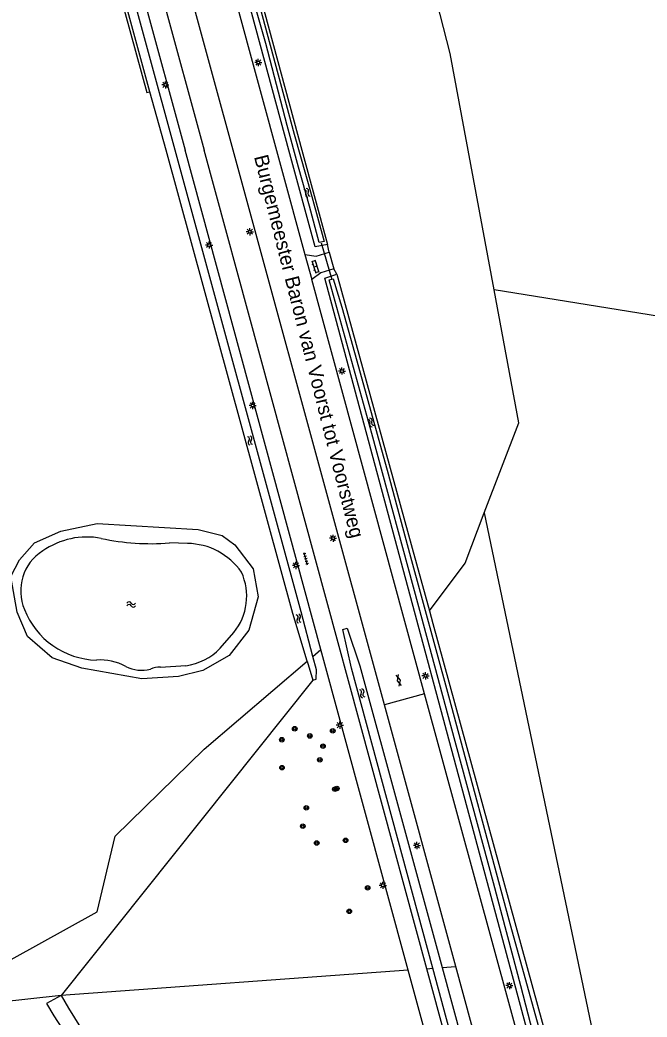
# Model space of a CAD drawing. Extents: x 128999 to 131010, y 395498 to 399007.
# Drawn here: x 129345.3 to 129455.1, y 397348.1 to 397522.8 of the extents above; entities that cross this region are included whole.
import ezdxf

# ---------------------------------------------------------------- set-up
doc = ezdxf.new("R2010")
doc.units = 0
for name, color, linetype in [('gg-afsc-faunaraster', 7, 'Continuous'), ('gg-anno-openbare ruimte label', 7, 'Continuous'), ('gg-knt-onverhard', 7, 'Continuous'), ('gg-knt-verharding', 7, 'Continuous'), ('gg-kntw-bovenkant insteek waterloop', 7, 'Continuous'), ('gg-kntw-waterlijn', 7, 'Continuous'), ('gg-kwrk-duiker nz buis', 7, 'Continuous'), ('gt-grn-groengrens', 7, 'Continuous'), ('gt-grn-vlakafsluiter', 7, 'Continuous'), ('gt-grn-weggrens', 7, 'Continuous'), ('gt-symb-boom', 7, 'Continuous'), ('gt-symb-gesloten verharding', 7, 'Continuous'), ('gt-symb-klinker verharding', 7, 'Continuous'), ('gt-symb-lichtmast', 7, 'Continuous'), ('gt-symb-tegel verharding', 7, 'Continuous'), ('gt-symb-watersymbool', 7, 'Continuous')]:
    doc.layers.add(name, color=color, linetype=linetype)

# ---------------------------------------------------------------- blocks, each defined once
blk = doc.blocks.new('gt0-BOOM')
at = {"layer": 'gt-symb-boom'}
for radius in [0.4, 0.2]:
    blk.add_circle((0, 0), radius, dxfattribs=at)
blk = doc.blocks.new('gt0-LMAST')
at = {"layer": 'gt-symb-lichtmast'}
for p, q in [((-0.18, 0.17), (-0.45, 0.44)), ((-0.01, 0.25), (-0.01, 0.62)), ((0.17, 0.17), (0.44, 0.44)), ((-0.26, 0), (-0.63, 0)), ((-0.18, -0.18), (-0.45, -0.45)), ((-0.01, -0.25), (-0.01, -0.63)), ((0.44, -0.45), (0.17, -0.18)), ((0.24, 0), (0.62, 0))]:
    blk.add_line(p, q, dxfattribs=at)
blk.add_circle((-0.01, 0), 0.25, dxfattribs=at)
blk = doc.blocks.new('gt0-WA')
at = {"layer": 'gt-symb-watersymbool'}
for centre, start, end in [((-0.32, 0.02), 28.0725, 151.9275), ((0.43, 0.42), 208.0725, 331.9275), ((-0.32, -0.43), 28.0725, 151.9275), ((0.43, -0.03), 208.0725, 331.9275)]:
    blk.add_arc(centre, 0.425, start, end, dxfattribs=at)
blk = doc.blocks.new('gt0-GESVH1')
at = {"layer": 'gt-symb-gesloten verharding'}
for p, q in [((-0.99, -0.26), (0.01, 0.24)), ((0.01, -0.26), (-0.99, 0.24)), ((0.01, 0.24), (1.01, -0.26)), ((1.01, 0.24), (0.01, -0.26))]:
    blk.add_line(p, q, dxfattribs=at)
blk = doc.blocks.new('gt0-TEG1')
at = {"layer": 'gt-symb-tegel verharding'}
for p, q in [((-1.12, 0), (1.12, 0)), ((-0.9, -0.25), (-0.9, 0.25)), ((-0.45, -0.25), (-0.45, 0.25)), ((0, -0.25), (0, 0.25)), ((0.45, -0.25), (0.45, 0.25)), ((0.9, -0.25), (0.9, 0.25))]:
    blk.add_line(p, q, dxfattribs=at)
blk = doc.blocks.new('gt0-KL1')
at = {"layer": 'gt-symb-klinker verharding'}
for p, q in [((-1.15, 0.3), (1.15, 0.3)), ((-1, -0.3), (-1, 0.3)), ((-0.5, 0.3), (-0.5, 0.45)), ((0, -0.3), (0, 0.3)), ((0.5, 0.3), (0.5, 0.45)), ((1, -0.3), (1, 0.3)), ((-1.15, -0.3), (1.15, -0.3)), ((-0.5, -0.45), (-0.5, -0.3)), ((0.5, -0.45), (0.5, -0.3))]:
    blk.add_line(p, q, dxfattribs=at)

msp = doc.modelspace()

# ---------------------------------------------------------------- linework, layer by layer
at = {"layer": 'gg-afsc-faunaraster'}
msp.add_lwpolyline([(129299.07, 397649.4), (129302.03, 397649.53), (129307.36, 397648.24), (129312.14, 397644.62), (129319.65, 397639.45), (129327.31, 397633.81), (129332.2, 397628.56), (129335.71, 397623.37), (129338.02, 397616.8), (129351.95, 397566.8), (129367.51, 397510.11)], dxfattribs=at)
at = {"layer": 'gg-knt-onverhard'}
for points in [[(129352.47, 397351.89), (129353.76, 397349.7), (129355.86, 397346.32)], [(129349.92, 397350.52), (129351.19, 397348.37), (129355.53, 397341.69), (129359.13, 397337.49), (129361.79, 397333.99), (129365.37, 397328.92), (129370.43, 397322.05), (129373.57, 397318.37), (129377.44, 397314.61), (129382.14, 397310.42), (129386.75, 397306.74), (129390.19, 397303.32), (129390.84, 397302.45)]]:
    msp.add_lwpolyline(points, dxfattribs=at)
at = {"layer": 'gg-knt-verharding'}
for p, q in [((129342.38, 397616.85), (129374.21, 397500)), ((129345.51, 397617.67), (129377.55, 397500)), ((129366.17, 397588.19), (129395.18, 397481.76)), ((129409.1, 397402.86), (129361.04, 397579.24)), ((129398, 397412.52), (129374.21, 397500)), ((129416.57, 397356.61), (129377.55, 397500)), ((129395.18, 397481.76), (129396.38, 397477.34)), ((129399.41, 397482.16), (129399.89, 397480.47)), ((129399.89, 397480.47), (129400.25, 397479.21)), ((129416.15, 397404.78), (129396.38, 397477.34)), ((129413.28, 397356.35), (129398, 397412.52)), ((129421.6, 397356.99), (129409.1, 397402.86)), ((129424.64, 397326.96), (129416.57, 397356.61)), ((129421.51, 397326.09), (129413.28, 397356.35))]:
    msp.add_line(p, q, dxfattribs=at)
for points in [[(129395.18, 397481.76), (129397.18, 397481.46), (129399.41, 397482.16)], [(129400.25, 397479.21), (129397.98, 397478.52), (129396.38, 397477.34)], [(129444.79, 397258.91), (129444.94, 397263.27), (129444.8, 397274.44), (129444.12, 397285.96), (129442.37, 397301.7), (129440.2, 397314.15), (129437.13, 397327.28), (129434.16, 397338.69), (129416.15, 397404.78)], [(129427.83, 397195.56), (129432.03, 397213.82), (129434.31, 397226.17), (129436.24, 397241.01), (129437.32, 397256.9), (129437.41, 397272.84), (129436.45, 397287.67), (129434.97, 397300.11), (129433, 397312.4), (129429.11, 397329.19), (129427.11, 397336.77), (129421.6, 397356.99)]]:
    msp.add_lwpolyline(points, dxfattribs=at)
at = {"layer": 'gg-kntw-bovenkant insteek waterloop'}
for p, q in [((129369.31, 397593.72), (129394.64, 397500)), ((129392.39, 397500), (129367.34, 397592.16)), ((129370.86, 397500), (129368.05, 397510.26)), ((129394.64, 397500), (129399.12, 397483.51)), ((129400.79, 397478.26), (129413.97, 397430.26)), ((129413.97, 397430.26), (129416.98, 397419.29)), ((129416.98, 397419.29), (129417.59, 397417.07)), ((129395.59, 397410.5), (129396.59, 397407.18)), ((129425.61, 397327.17), (129417.59, 397356.69)), ((129419.21, 397356.81), (129427.18, 397327.55))]:
    msp.add_line(p, q, dxfattribs=at)
for points in [[(129368.05, 397510.26), (129338.86, 397616.87), (129336.71, 397622.9)], [(129372.45, 397500), (129340.43, 397617.29), (129338.11, 397623.53)], [(129395.59, 397410.5), (129393.09, 397418.82), (129370.86, 397500)], [(129396.59, 397411.33), (129394.54, 397419.11), (129372.45, 397500)], [(129399.12, 397483.51), (129396.99, 397483.06), (129392.39, 397500)], [(129446.52, 397258.94), (129446.6, 397261.76), (129446.64, 397265.61), (129446.61, 397269.47), (129446.52, 397273.02), (129446.38, 397276.58), (129446.19, 397280.13), (129445.94, 397283.68), (129445.61, 397287.55), (129445.21, 397291.41), (129444.27, 397299.12), (129443.25, 397306.24), (129442.67, 397309.79), (129442.03, 397313.33), (129441.31, 397316.91), (129440.53, 397320.47), (129438.88, 397327.57), (129437.43, 397333.44), (129435.89, 397339.3), (129398.65, 397477.58), (129400.79, 397478.26)], [(129376.5, 397433.58), (129380.7, 397432.48), (129382.93, 397430.88), (129386.13, 397426.66), (129386.97, 397421.78), (129385.36, 397415.89), (129381.92, 397411.5), (129377.31, 397408.84), (129373.04, 397407.77), (129366.6, 397407.37), (129356.13, 397409.28), (129350.93, 397411.08), (129346.58, 397414.83), (129344.8, 397419.06), (129343.66, 397425.31), (129345.22, 397428.24), (129347.82, 397431.23), (129352.41, 397433.27), (129358.81, 397434.6), (129376.5, 397433.58)], [(129417.59, 397356.69), (129403.32, 397409.27), (129401.85, 397416.04), (129402.6, 397416.25), (129404.82, 397409.65), (129419.21, 397356.81)], [(129417.59, 397417.07), (129441.73, 397329.16), (129442.61, 397325.6), (129444.09, 397318.9), (129444.94, 397314.61)], [(129396.59, 397407.18), (129397.14, 397407.32), (129397.22, 397408.94), (129396.59, 397411.33)]]:
    msp.add_lwpolyline(points, dxfattribs=at)
at = {"layer": 'gg-kntw-waterlijn'}
for p, q in [((129374.6, 397431.11), (129371.44, 397431.21)), ((129380.34, 397412.75), (129382.71, 397415.5)), ((129369.9, 397409.45), (129374.31, 397409.7))]:
    msp.add_line(p, q, dxfattribs=at)
for points in [[(129366.63, 397597.43), (129367.42, 397597.63), (129370.04, 397588.2), (129375.64, 397568.27), (129379.82, 397552.53), (129386.29, 397528.89), (129393.28, 397502.79), (129396.41, 397491.87), (129398.53, 397484.01), (129397.66, 397483.82), (129396.01, 397490.18), (129394.05, 397497.04), (129392.05, 397504.34), (129388.32, 397518.68), (129382.13, 397540.42), (129371.57, 397579.87), (129366.63, 397597.43)], [(129399.42, 397477.27), (129400.13, 397477.47), (129401.67, 397472.5), (129404.3, 397463.1), (129409.74, 397443.29), (129413.49, 397429.4), (129420.32, 397404.39), (129430.88, 397365.15), (129436.64, 397344.53), (129441.23, 397327.1), (129444.02, 397314.1), (129446.49, 397301.34), (129447.26, 397295.68)], [(129441.89, 397319.86), (129436, 397342.07), (129432.99, 397353.62), (129428.21, 397371.62), (129420.73, 397399.21), (129415.14, 397420.03), (129406.9, 397450.37), (129399.89, 397475.61), (129399.42, 397477.27)]]:
    msp.add_lwpolyline(points, dxfattribs=at)
for centre, radius, start, end in [((129356.99, 397418.79), 13.45, 79.1409, 125.0746), ((129368.12, 397471.54), 40.47, 257.7377, 274.7025), ((129374.46, 397419.45), 11.66, 34.5527, 89.3469), ((129353.7, 397422.79), 8.3, 122.3314, 203.0775), ((129374.97, 397421.87), 10.02, 320.5443, 24.7774), ((129359.02, 397424.58), 13.9, 201.2657, 268.6218), ((129373.01, 397419.75), 10.14, 277.3426, 316.2878), ((129359.35, 397401.41), 9.29, 61.3634, 94.108), ((129366.58, 397414.95), 6.05, 242.7594, 284.7326), ((129369.9, 397404.74), 4.71, 89.9931, 112.2562)]:
    msp.add_arc(centre, radius, start, end, dxfattribs=at)
at = {"layer": 'gg-kwrk-duiker nz buis'}
msp.add_line((129399.97, 397477.31), (129398.1, 397483.72), dxfattribs=at)
at = {"layer": 'gt-grn-groengrens'}
for p, q in [((129399.41, 397482.16), (129399.12, 397483.51)), ((129400.79, 397478.26), (129400.25, 397479.21)), ((129432.64, 397452.26), (129428.31, 397475.56)), ((129466.03, 397469.46), (129428.31, 397475.56)), ((129426.61, 397436.46), (129432.64, 397452.26)), ((129423.25, 397427.65), (129426.61, 397436.46)), ((129426.61, 397436.46), (129451.9, 397315.3)), ((129416.98, 397419.29), (129423.25, 397427.65)), ((129396.59, 397411.33), (129398, 397412.52)), ((129416.57, 397356.61), (129417.59, 397356.69)), ((129419.21, 397356.81), (129421.6, 397356.99)), ((129413.28, 397356.35), (129352.47, 397351.89)), ((129352.47, 397351.89), (129328.78, 397349.35))]:
    msp.add_line(p, q, dxfattribs=at)
for points in [[(129428.31, 397475.56), (129420.6, 397516.95), (129392.74, 397625.87)], [(129343.72, 397358.24), (129358.82, 397366.57), (129361.94, 397379.83), (129377.54, 397395.04), (129395.59, 397410.5)]]:
    msp.add_lwpolyline(points, dxfattribs=at)
at = {"layer": 'gt-grn-vlakafsluiter'}
for p, q in [((129367.51, 397510.11), (129368.05, 397510.26)), ((129396.59, 397407.18), (129352.47, 397351.89)), ((129352.47, 397351.89), (129349.92, 397350.52))]:
    msp.add_line(p, q, dxfattribs=at)
at = {"layer": 'gt-grn-weggrens'}
msp.add_line((129416.15, 397404.78), (129409.1, 397402.86), dxfattribs=at)

# ---------------------------------------------------------------- block references
at = {"layer": 'gt-symb-boom'}
for p in [(129393.4, 397398.65), (129400.06, 397398.28), (129391.14, 397396.72), (129396.05, 397397.39), (129398.35, 397395.6), (129397.79, 397393.2), (129391.17, 397391.83), (129400.44, 397388.06), (129400.77, 397388.17), (129395.43, 397384.79), (129394.81, 397381.57), (129402.31, 397379.09), (129397.26, 397378.62), (129406.17, 397370.77), (129402.95, 397366.66)]:
    msp.add_blockref('gt0-BOOM', p, dxfattribs=at)
at = {"layer": 'gt-symb-gesloten verharding', "rotation": -74.75492966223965}
msp.add_blockref('gt0-GESVH1', (129411.63, 397407.13), dxfattribs=at)
at = {"layer": 'gt-symb-klinker verharding', "rotation": -71.9999254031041}
msp.add_blockref('gt0-KL1', (129397.01, 397479.63), dxfattribs=at)
at = {"layer": 'gt-symb-lichtmast'}
for p in [(129387.02, 397515.38), (129370.75, 397511.44), (129385.54, 397485.72), (129378.41, 397483.39), (129401.69, 397461.32), (129386.04, 397455.29), (129400.12, 397432.02), (129393.62, 397427.26), (129416.31, 397407.91), (129401.31, 397399.28), (129414.81, 397378.19), (129408.85, 397371.21), (129431.01, 397353.64)]:
    msp.add_blockref('gt0-LMAST', p, dxfattribs=at)
at = {"layer": 'gt-symb-tegel verharding', "rotation": 104.89818725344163}
msp.add_blockref('gt0-TEG1', (129395.35, 397428.4), dxfattribs=at)
at = {"layer": 'gt-symb-watersymbool'}
for p, rotation in [((129395.58, 397492.49), 117.38497058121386), ((129406.76, 397452.27), 122.33937708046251), ((129385.56, 397449.2), -74.75492966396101), ((129364.82, 397420.4), 180), ((129394.07, 397418.01), -74.99108632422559), ((129405.21, 397404.9), -69.75249849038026)]:
    msp.add_blockref('gt0-WA', p, dxfattribs=dict(at, rotation=rotation))

# ---------------------------------------------------------------- texts
at = {"layer": 'gg-anno-openbare ruimte label'}
msp.add_text('Burgemeester Baron van Voorst tot Voorstweg', height=2.5, rotation=284.2, dxfattribs=at).set_placement((129386.25, 397498.86))

doc.saveas('drawing.dxf')
